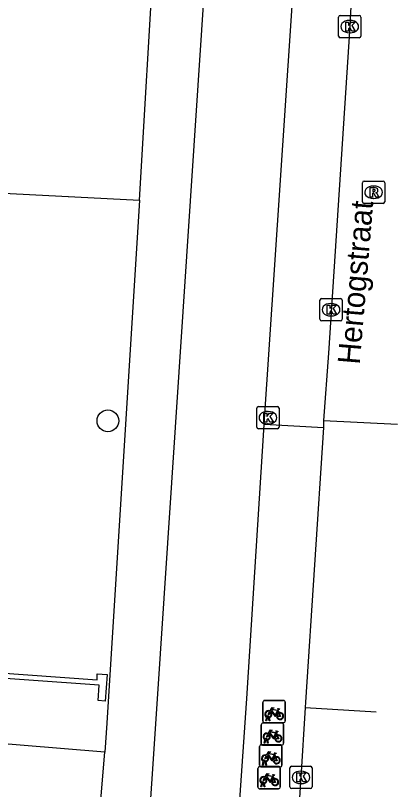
# Model space of a CAD drawing. Extents: x 161087 to 161922, y 382574 to 383873.
# Drawn here: x 161852.97 to 161870.14, y 382747.01 to 382781.78 of the extents above; entities that cross this region are included whole.
import ezdxf

# ---------------------------------------------------------------- set-up
doc = ezdxf.new("R2010")
doc.units = 0
for name, color, linetype in [('IMGEO_Berm_open', 7, 'Continuous'), ('IMGEO_Boom', 7, 'Continuous'), ('IMGEO_Fietsenrek', 7, 'Continuous'), ('IMGEO_Fietspad_gesloten', 7, 'Continuous'), ('IMGEO_Kolk', 7, 'Continuous'), ('IMGEO_Muur', 7, 'Continuous'), ('IMGEO_Openbare_ruimte_label', 7, 'Continuous'), ('IMGEO_Pand', 7, 'Continuous'), ('IMGEO_Rijbaan_lokaal_gesloten', 7, 'Continuous'), ('IMGEO_Rijbaan_lokaal_open', 7, 'Continuous'), ('IMGEO_Rioolput', 7, 'Continuous'), ('IMGEO_Voetpad_open', 7, 'Continuous')]:
    doc.layers.add(name, color=color, linetype=linetype)

msp = doc.modelspace()

# ---------------------------------------------------------------- linework, layer by layer
at = {"layer": 'IMGEO_Berm_open'}
msp.add_lwpolyline([(161864.145, 382763.415), (161866.811, 382763.275)], dxfattribs=at)
at = {"layer": 'IMGEO_Boom'}
msp.add_circle((161857.12, 382763.571), 0.489, dxfattribs=at)
at = {"layer": 'IMGEO_Fietsenrek'}
for p, q in [((161864.092, 382750.087), (161864.092, 382750.928)), ((161864.092, 382750.928), (161864.092, 382750.087)), ((161864.167, 382751.012), (161865.008, 382751.012)), ((161865.008, 382751.012), (161864.167, 382751.012)), ((161865.092, 382750.937), (161865.092, 382750.096)), ((161865.092, 382750.096), (161865.092, 382750.937)), ((161864.779, 382750.561), (161864.815, 382750.466)), ((161864.219, 382750.096), (161864.258, 382750.256)), ((161864.253, 382750.096), (161864.219, 382750.096)), ((161864.288, 382750.244), (161864.253, 382750.096)), ((161864.33, 382750.268), (161864.329, 382750.272)), ((161864.371, 382750.096), (161864.337, 382750.238)), ((161864.361, 382750.279), (161864.362, 382750.272)), ((161864.369, 382750.242), (161864.404, 382750.096)), ((161864.404, 382750.096), (161864.371, 382750.096)), ((161864.016, 382749.08), (161864.016, 382749.921)), ((161864.016, 382749.921), (161864.016, 382749.08)), ((161864.091, 382750.005), (161864.932, 382750.005)), ((161864.932, 382750.005), (161864.091, 382750.005)), ((161865.017, 382750.012), (161864.176, 382750.012)), ((161864.176, 382750.012), (161865.017, 382750.012)), ((161865.016, 382749.93), (161865.016, 382749.089)), ((161865.016, 382749.089), (161865.016, 382749.93)), ((161864.703, 382749.554), (161864.739, 382749.459)), ((161864.017, 382749.026), (161864.858, 382749.026)), ((161864.858, 382749.026), (161864.017, 382749.026)), ((161864.941, 382749.005), (161864.1, 382749.005)), ((161864.1, 382749.005), (161864.941, 382749.005)), ((161864.143, 382749.089), (161864.182, 382749.249)), ((161864.177, 382749.089), (161864.143, 382749.089)), ((161864.212, 382749.237), (161864.177, 382749.089)), ((161864.254, 382749.261), (161864.253, 382749.265)), ((161864.295, 382749.089), (161864.261, 382749.231)), ((161864.285, 382749.272), (161864.286, 382749.265)), ((161864.293, 382749.235), (161864.328, 382749.089)), ((161864.328, 382749.089), (161864.295, 382749.089)), ((161863.942, 382748.101), (161863.942, 382748.942)), ((161863.942, 382748.942), (161863.942, 382748.101)), ((161864.942, 382748.951), (161864.942, 382748.11)), ((161864.942, 382748.11), (161864.942, 382748.951)), ((161864.629, 382748.575), (161864.665, 382748.48)), ((161863.868, 382747.122), (161863.868, 382747.963)), ((161863.868, 382747.963), (161863.868, 382747.122)), ((161863.943, 382748.047), (161864.784, 382748.047)), ((161864.784, 382748.047), (161863.943, 382748.047)), ((161864.867, 382748.026), (161864.026, 382748.026)), ((161864.026, 382748.026), (161864.867, 382748.026)), ((161864.069, 382748.11), (161864.108, 382748.27)), ((161864.103, 382748.11), (161864.069, 382748.11)), ((161864.138, 382748.258), (161864.103, 382748.11)), ((161864.18, 382748.282), (161864.179, 382748.286)), ((161864.221, 382748.11), (161864.187, 382748.252)), ((161864.211, 382748.293), (161864.212, 382748.286)), ((161864.219, 382748.256), (161864.254, 382748.11)), ((161864.254, 382748.11), (161864.221, 382748.11)), ((161864.868, 382747.972), (161864.868, 382747.131)), ((161864.868, 382747.131), (161864.868, 382747.972)), ((161863.995, 382747.131), (161864.034, 382747.291)), ((161864.064, 382747.279), (161864.029, 382747.131)), ((161864.106, 382747.303), (161864.105, 382747.307)), ((161864.147, 382747.131), (161864.113, 382747.273)), ((161864.137, 382747.314), (161864.138, 382747.307)), ((161864.145, 382747.277), (161864.18, 382747.131)), ((161864.555, 382747.596), (161864.591, 382747.501)), ((161864.793, 382747.047), (161863.952, 382747.047)), ((161863.952, 382747.047), (161864.793, 382747.047)), ((161864.029, 382747.131), (161863.995, 382747.131)), ((161864.18, 382747.131), (161864.147, 382747.131))]:
    msp.add_line(p, q, dxfattribs=at)
for points in [[(161864.426, 382750.486), (161864.374, 382750.396), (161864.334, 382750.371), (161864.335, 382750.418), (161864.39, 382750.512)], [(161864.405, 382750.538), (161864.5, 382750.702), (161864.586, 382750.688), (161864.588, 382750.679), (161864.532, 382750.668), (161864.505, 382750.623), (161864.761, 382750.582)], [(161864.701, 382750.294), (161864.651, 382750.294), (161864.46, 382750.545), (161864.441, 382750.513)], [(161864.748, 382750.557), (161864.491, 382750.598), (161864.474, 382750.569), (161864.641, 382750.349), (161864.748, 382750.557)], [(161864.796, 382750.459), (161864.766, 382750.536), (161864.657, 382750.318), (161864.7, 382750.318)], [(161864.73, 382750.318), (161864.85, 382750.317), (161864.806, 382750.431)], [(161864.826, 382750.438), (161864.881, 382750.293), (161864.731, 382750.293)], [(161864.761, 382750.582), (161864.786, 382750.631), (161864.78, 382750.635), (161864.757, 382750.639), (161864.745, 382750.646), (161864.744, 382750.649), (161864.746, 382750.654), (161864.841, 382750.639), (161864.843, 382750.629), (161864.833, 382750.616), (161864.821, 382750.61), (161864.807, 382750.616), (161864.779, 382750.561)], [(161864.329, 382749.531), (161864.424, 382749.695), (161864.51, 382749.681), (161864.512, 382749.672), (161864.456, 382749.661), (161864.429, 382749.616), (161864.685, 382749.575)], [(161864.35, 382749.479), (161864.298, 382749.389), (161864.258, 382749.364), (161864.259, 382749.411), (161864.314, 382749.505)], [(161864.625, 382749.287), (161864.575, 382749.287), (161864.384, 382749.538), (161864.365, 382749.506)], [(161864.672, 382749.55), (161864.415, 382749.591), (161864.398, 382749.562), (161864.565, 382749.342), (161864.672, 382749.55)], [(161864.72, 382749.452), (161864.69, 382749.529), (161864.581, 382749.311), (161864.624, 382749.311)], [(161864.654, 382749.311), (161864.774, 382749.31), (161864.73, 382749.424)], [(161864.75, 382749.431), (161864.805, 382749.286), (161864.655, 382749.286)], [(161864.685, 382749.575), (161864.71, 382749.624), (161864.704, 382749.628), (161864.681, 382749.632), (161864.669, 382749.639), (161864.668, 382749.642), (161864.67, 382749.647), (161864.765, 382749.632), (161864.767, 382749.622), (161864.757, 382749.609), (161864.745, 382749.603), (161864.731, 382749.609), (161864.703, 382749.554)], [(161864.255, 382748.552), (161864.35, 382748.716), (161864.436, 382748.702), (161864.438, 382748.693), (161864.382, 382748.682), (161864.355, 382748.637), (161864.611, 382748.596)], [(161864.611, 382748.596), (161864.636, 382748.645), (161864.63, 382748.649), (161864.607, 382748.653), (161864.595, 382748.66), (161864.594, 382748.663), (161864.596, 382748.668), (161864.691, 382748.653), (161864.693, 382748.643), (161864.683, 382748.63), (161864.671, 382748.624), (161864.657, 382748.63), (161864.629, 382748.575)], [(161864.276, 382748.5), (161864.224, 382748.41), (161864.184, 382748.385), (161864.185, 382748.432), (161864.24, 382748.526)], [(161864.551, 382748.308), (161864.501, 382748.308), (161864.31, 382748.559), (161864.291, 382748.527)], [(161864.598, 382748.571), (161864.341, 382748.612), (161864.324, 382748.583), (161864.491, 382748.363), (161864.598, 382748.571)], [(161864.646, 382748.473), (161864.616, 382748.55), (161864.507, 382748.332), (161864.55, 382748.332)], [(161864.58, 382748.332), (161864.7, 382748.331), (161864.656, 382748.445)], [(161864.676, 382748.452), (161864.731, 382748.307), (161864.581, 382748.307)], [(161864.181, 382747.573), (161864.276, 382747.737), (161864.362, 382747.723), (161864.364, 382747.714), (161864.308, 382747.703), (161864.281, 382747.658), (161864.537, 382747.617)], [(161864.524, 382747.592), (161864.267, 382747.633), (161864.25, 382747.604), (161864.417, 382747.384), (161864.524, 382747.592)], [(161864.537, 382747.617), (161864.562, 382747.666), (161864.556, 382747.67), (161864.533, 382747.674), (161864.521, 382747.681), (161864.52, 382747.684), (161864.522, 382747.689), (161864.617, 382747.674), (161864.619, 382747.664), (161864.609, 382747.651), (161864.597, 382747.645), (161864.583, 382747.651), (161864.555, 382747.596)], [(161864.202, 382747.521), (161864.15, 382747.431), (161864.11, 382747.406), (161864.111, 382747.453), (161864.166, 382747.547)], [(161864.477, 382747.329), (161864.427, 382747.329), (161864.236, 382747.58), (161864.217, 382747.548)], [(161864.572, 382747.494), (161864.542, 382747.571), (161864.433, 382747.353), (161864.476, 382747.353)], [(161864.506, 382747.353), (161864.626, 382747.352), (161864.582, 382747.466)], [(161864.602, 382747.473), (161864.657, 382747.328), (161864.507, 382747.328)]]:
    msp.add_lwpolyline(points, dxfattribs=at)
for centre, radius, start, end in [((161864.17, 382750.934), 0.0779, 92.4484, 184.2845), ((161864.17, 382750.934), 0.0779, 92.4484, 184.2845), ((161865.014, 382750.934), 0.0779, 2.4484, 94.2845), ((161865.014, 382750.934), 0.0779, 2.4484, 94.2845), ((161864.332, 382750.397), 0.159, 62.6766, 242.1369), ((161864.332, 382750.397), 0.129, 63.3192, 238.903), ((161864.332, 382750.397), 0.129, 283.6043, 43.4302), ((161864.332, 382750.397), 0.159, 283.5766, 46.6042), ((161864.859, 382750.313), 0.159, 113.3408, 178.3217), ((161864.859, 382750.313), 0.159, 187.0065, 105.7708), ((161864.859, 382750.313), 0.129, 113.923, 177.9556), ((161864.859, 382750.313), 0.129, 188.6715, 104.5883), ((161864.17, 382750.09), 0.0779, 182.4484, 274.2845), ((161864.17, 382750.09), 0.0779, 182.4484, 274.2845), ((161864.312, 382750.268), 0.0499, 12.8025, 158.6934), ((161864.332, 382750.397), 0.159, 253.9967, 271.7867), ((161864.312, 382750.268), 0.0174, 12.8025, 163.4502), ((161864.332, 382750.397), 0.129, 253.415, 269.0204), ((161865.014, 382750.09), 0.0779, 272.4484, 4.2845), ((161865.014, 382750.09), 0.0779, 272.4484, 4.2845), ((161864.094, 382749.927), 0.0779, 92.4484, 184.2845), ((161864.094, 382749.927), 0.0779, 92.4484, 184.2845), ((161864.938, 382749.927), 0.0779, 2.4484, 94.2845), ((161864.938, 382749.927), 0.0779, 2.4484, 94.2845), ((161864.256, 382749.39), 0.159, 62.6766, 242.1369), ((161864.256, 382749.39), 0.129, 63.3192, 238.903), ((161864.256, 382749.39), 0.129, 283.6043, 43.4302), ((161864.256, 382749.39), 0.159, 283.5766, 46.6042), ((161864.783, 382749.306), 0.159, 113.3408, 178.3217), ((161864.783, 382749.306), 0.159, 187.0065, 105.7708), ((161864.783, 382749.306), 0.129, 113.923, 177.9556), ((161864.783, 382749.306), 0.129, 188.6715, 104.5883), ((161864.02, 382748.948), 0.0779, 92.4484, 184.2845), ((161864.02, 382748.948), 0.0779, 92.4484, 184.2845), ((161864.094, 382749.083), 0.0779, 182.4484, 274.2845), ((161864.094, 382749.083), 0.0779, 182.4484, 274.2845), ((161864.236, 382749.261), 0.0499, 12.8025, 158.6934), ((161864.256, 382749.39), 0.159, 253.9967, 271.7867), ((161864.236, 382749.261), 0.0174, 12.8025, 163.4502), ((161864.256, 382749.39), 0.129, 253.415, 269.0204), ((161864.864, 382748.948), 0.0779, 2.4484, 94.2845), ((161864.864, 382748.948), 0.0779, 2.4484, 94.2845), ((161864.938, 382749.083), 0.0779, 272.4484, 4.2845), ((161864.938, 382749.083), 0.0779, 272.4484, 4.2845), ((161864.182, 382748.411), 0.159, 62.6766, 242.1369), ((161864.182, 382748.411), 0.129, 63.3192, 238.903), ((161864.162, 382748.282), 0.0499, 12.8025, 158.6934), ((161864.162, 382748.282), 0.0174, 12.8025, 163.4502), ((161864.182, 382748.411), 0.129, 283.6043, 43.4302), ((161864.182, 382748.411), 0.159, 283.5766, 46.6042), ((161864.709, 382748.327), 0.159, 113.3408, 178.3217), ((161864.709, 382748.327), 0.159, 187.0065, 105.7708), ((161864.709, 382748.327), 0.129, 113.923, 177.9556), ((161864.709, 382748.327), 0.129, 188.6715, 104.5883), ((161863.946, 382747.969), 0.0779, 92.4484, 184.2845), ((161863.946, 382747.969), 0.0779, 92.4484, 184.2845), ((161864.02, 382748.104), 0.0779, 182.4484, 274.2845), ((161864.02, 382748.104), 0.0779, 182.4484, 274.2845), ((161864.182, 382748.411), 0.159, 253.9967, 271.7867), ((161864.182, 382748.411), 0.129, 253.415, 269.0204), ((161864.79, 382747.969), 0.0779, 2.4484, 94.2845), ((161864.79, 382747.969), 0.0779, 2.4484, 94.2845), ((161864.864, 382748.104), 0.0779, 272.4484, 4.2845), ((161864.864, 382748.104), 0.0779, 272.4484, 4.2845), ((161864.108, 382747.432), 0.159, 62.6766, 242.1369), ((161864.108, 382747.432), 0.129, 63.3192, 238.903), ((161864.088, 382747.303), 0.0499, 12.8025, 158.6934), ((161864.108, 382747.432), 0.159, 253.9967, 271.7867), ((161864.088, 382747.303), 0.0174, 12.8025, 163.4502), ((161864.108, 382747.432), 0.129, 253.415, 269.0204), ((161864.108, 382747.432), 0.129, 283.6043, 43.4302), ((161864.108, 382747.432), 0.159, 283.5766, 46.6042), ((161864.635, 382747.348), 0.159, 113.3408, 178.3217), ((161864.635, 382747.348), 0.159, 187.0065, 105.7708), ((161864.635, 382747.348), 0.129, 113.923, 177.9556), ((161864.635, 382747.348), 0.129, 188.6715, 104.5883), ((161863.946, 382747.125), 0.0779, 182.4484, 274.2845), ((161863.946, 382747.125), 0.0779, 182.4484, 274.2845), ((161864.79, 382747.125), 0.0779, 272.4484, 4.2845), ((161864.79, 382747.125), 0.0779, 272.4484, 4.2845)]:
    msp.add_arc(centre, radius, start, end, dxfattribs=at)
at = {"layer": 'IMGEO_Fietspad_gesloten'}
for points in [[(161864.583, 382830.709), (161862.087, 382792.658), (161859.377, 382751.761), (161858.204, 382734.049)], [(161864.145, 382763.415), (161865.585, 382784.899)], [(161862.676, 382741.127), (161863.359, 382751.101), (161864.144, 382763.393), (161864.145, 382763.415)]]:
    msp.add_lwpolyline(points, dxfattribs=at)
at = {"layer": 'IMGEO_Kolk'}
for p, q in [((161867.491, 382780.851), (161867.491, 382781.703)), ((161867.566, 382781.777), (161868.418, 382781.777)), ((161868.492, 382781.703), (161868.492, 382780.851)), ((161867.979, 382781.557), (161868.004, 382781.557)), ((161868.002, 382780.997), (161867.977, 382780.997)), ((161868.418, 382780.777), (161867.566, 382780.777)), ((161866.652, 382768.136), (161866.652, 382768.988)), ((161866.727, 382769.062), (161867.579, 382769.062)), ((161867.14, 382768.842), (161867.165, 382768.842)), ((161867.653, 382768.988), (161867.653, 382768.136)), ((161867.163, 382768.282), (161867.138, 382768.282)), ((161867.579, 382768.062), (161866.727, 382768.062)), ((161863.814, 382763.288), (161863.814, 382764.14)), ((161863.889, 382764.214), (161864.741, 382764.214)), ((161864.302, 382763.994), (161864.327, 382763.994)), ((161864.815, 382764.14), (161864.815, 382763.288)), ((161864.325, 382763.434), (161864.3, 382763.434)), ((161864.741, 382763.214), (161863.889, 382763.214)), ((161865.3, 382747.131), (161865.3, 382747.983)), ((161865.375, 382748.057), (161866.227, 382748.057)), ((161866.301, 382747.983), (161866.301, 382747.131)), ((161865.788, 382747.837), (161865.813, 382747.837)), ((161865.811, 382747.277), (161865.786, 382747.277)), ((161866.227, 382747.057), (161865.375, 382747.057))]:
    msp.add_line(p, q, dxfattribs=at)
for points in [[(161867.491, 382780.851), (161867.491, 382781.703)], [(161867.566, 382781.777), (161868.418, 382781.777)], [(161868.492, 382781.703), (161868.492, 382780.851)], [(161867.812, 382781.477), (161867.935, 382781.477), (161867.935, 382781.326), (161868.065, 382781.477), (161868.229, 382781.477), (161868.083, 382781.326), (161868.236, 382781.077), (161868.084, 382781.077), (161867.999, 382781.241), (161867.935, 382781.174), (161867.935, 382781.077), (161867.812, 382781.077), (161867.812, 382781.477)], [(161868.418, 382780.777), (161867.566, 382780.777)], [(161866.652, 382768.136), (161866.652, 382768.988)], [(161866.727, 382769.062), (161867.579, 382769.062)], [(161867.653, 382768.988), (161867.653, 382768.136)], [(161866.973, 382768.762), (161867.096, 382768.762), (161867.096, 382768.611), (161867.226, 382768.762), (161867.39, 382768.762), (161867.244, 382768.611), (161867.397, 382768.362), (161867.245, 382768.362), (161867.16, 382768.526), (161867.096, 382768.459), (161867.096, 382768.362), (161866.973, 382768.362), (161866.973, 382768.762)], [(161867.579, 382768.062), (161866.727, 382768.062)], [(161863.814, 382763.288), (161863.814, 382764.14)], [(161863.889, 382764.214), (161864.741, 382764.214)], [(161864.815, 382764.14), (161864.815, 382763.288)], [(161864.135, 382763.914), (161864.258, 382763.914), (161864.258, 382763.763), (161864.388, 382763.914), (161864.552, 382763.914), (161864.406, 382763.763), (161864.559, 382763.514), (161864.407, 382763.514), (161864.322, 382763.678), (161864.258, 382763.611), (161864.258, 382763.514), (161864.135, 382763.514), (161864.135, 382763.914)], [(161864.741, 382763.214), (161863.889, 382763.214)], [(161865.3, 382747.131), (161865.3, 382747.983)], [(161865.375, 382748.057), (161866.227, 382748.057)], [(161866.301, 382747.983), (161866.301, 382747.131)], [(161865.621, 382747.757), (161865.744, 382747.757), (161865.744, 382747.606), (161865.874, 382747.757), (161866.038, 382747.757), (161865.892, 382747.606), (161866.045, 382747.357), (161865.893, 382747.357), (161865.808, 382747.521), (161865.744, 382747.454), (161865.744, 382747.357), (161865.621, 382747.357), (161865.621, 382747.757)], [(161866.227, 382747.057), (161865.375, 382747.057)]]:
    msp.add_lwpolyline(points, dxfattribs=at)
for centre, start, end in [((161867.568, 382781.701), 91.552, 178.448), ((161867.568, 382781.701), 91.552, 178.448), ((161868.416, 382781.701), 1.552, 88.448), ((161868.416, 382781.701), 1.552, 88.448), ((161867.568, 382780.853), 181.552, 268.448), ((161867.568, 382780.853), 181.552, 268.448), ((161868.416, 382780.853), 271.552, 358.448), ((161868.416, 382780.853), 271.552, 358.448), ((161866.729, 382768.986), 91.552, 178.448), ((161866.729, 382768.986), 91.552, 178.448), ((161867.577, 382768.986), 1.552, 88.448), ((161867.577, 382768.986), 1.552, 88.448), ((161866.729, 382768.138), 181.552, 268.448), ((161866.729, 382768.138), 181.552, 268.448), ((161867.577, 382768.138), 271.552, 358.448), ((161867.577, 382768.138), 271.552, 358.448), ((161863.891, 382764.138), 91.552, 178.448), ((161863.891, 382764.138), 91.552, 178.448), ((161864.739, 382764.138), 1.552, 88.448), ((161864.739, 382764.138), 1.552, 88.448), ((161863.891, 382763.29), 181.552, 268.448), ((161863.891, 382763.29), 181.552, 268.448), ((161864.739, 382763.29), 271.552, 358.448), ((161864.739, 382763.29), 271.552, 358.448), ((161865.377, 382747.981), 91.552, 178.448), ((161865.377, 382747.981), 91.552, 178.448), ((161866.225, 382747.981), 1.552, 88.448), ((161866.225, 382747.981), 1.552, 88.448), ((161865.377, 382747.133), 181.552, 268.448), ((161865.377, 382747.133), 181.552, 268.448), ((161866.225, 382747.133), 271.552, 358.448), ((161866.225, 382747.133), 271.552, 358.448)]:
    msp.add_arc(centre, 0.0765, start, end, dxfattribs=at)
for centre, major_axis, ratio, start_param, end_param in [((161867.978, 382781.277), (-0.387, 0.002), 0.722429, 4.712389, 7.853982), ((161868.003, 382781.277), (-0.39, 0.002), 0.717154, 1.570796, 4.712389), ((161867.139, 382768.562), (-0.387, 0.002), 0.722429, 4.712389, 7.853982), ((161867.164, 382768.562), (-0.39, 0.002), 0.717154, 1.570796, 4.712389), ((161864.301, 382763.714), (-0.387, 0.002), 0.722429, 4.712389, 7.853982), ((161864.326, 382763.714), (-0.39, 0.002), 0.717154, 1.570796, 4.712389), ((161865.787, 382747.557), (-0.387, 0.002), 0.722429, 4.712389, 7.853982), ((161865.812, 382747.557), (-0.39, 0.002), 0.717154, 1.570796, 4.712389)]:
    msp.add_ellipse(centre, major_axis=major_axis, ratio=ratio, start_param=start_param, end_param=end_param, dxfattribs=at)
at = {"layer": 'IMGEO_Muur'}
msp.add_lwpolyline([(161844.36, 382752.828), (161856.644, 382751.943), (161856.643, 382752.212), (161857.081, 382752.181), (161856.997, 382750.984), (161856.678, 382751.007), (161856.728, 382751.706), (161844.482, 382752.573)], dxfattribs=at)
at = {"layer": 'IMGEO_Pand'}
for points in [[(161858.54, 382773.49), (161859.223, 382784.937), (161859.25, 382785.386)], [(161849.885, 382776.163), (161850.038, 382778.234), (161852.437, 382778.057), (161852.125, 382773.811), (161858.54, 382773.49)], [(161856.985, 382748.691), (161845.906, 382749.6)], [(161856.266, 382740.106), (161856.985, 382748.691)]]:
    msp.add_lwpolyline(points, dxfattribs=at)
at = {"layer": 'IMGEO_Rijbaan_lokaal_gesloten'}
for points in [[(161868.195, 382784.741), (161868.059, 382782.507), (161867.992, 382781.277), (161867.032, 382766.607), (161866.818, 382763.59)], [(161866.818, 382763.59), (161870.141, 382763.42)], [(161865.994, 382750.69), (161865.801, 382747.557), (161865.365, 382740.966)], [(161865.994, 382750.69), (161869.18, 382750.506)]]:
    msp.add_lwpolyline(points, dxfattribs=at)
at = {"layer": 'IMGEO_Rijbaan_lokaal_open'}
for points in [[(161866.811, 382763.275), (161866.01, 382750.942), (161865.994, 382750.69)], [(161866.818, 382763.59), (161866.811, 382763.275)]]:
    msp.add_lwpolyline(points, dxfattribs=at)
at = {"layer": 'IMGEO_Rioolput'}
for p, q in [((161868.565, 382773.411), (161868.565, 382774.263)), ((161868.64, 382774.337), (161869.492, 382774.337)), ((161869.053, 382774.117), (161869.078, 382774.117)), ((161869.566, 382774.263), (161869.566, 382773.411)), ((161869.492, 382773.337), (161868.64, 382773.337)), ((161869.076, 382773.557), (161869.051, 382773.557))]:
    msp.add_line(p, q, dxfattribs=at)
for points in [[(161868.565, 382773.411), (161868.565, 382774.263)], [(161868.64, 382774.337), (161869.492, 382774.337)], [(161869.154, 382774.035), (161868.902, 382774.037), (161868.902, 382773.637)], [(161869.566, 382774.263), (161869.566, 382773.411)], [(161868.902, 382773.637), (161869.026, 382773.637), (161869.026, 382773.799), (161869.037, 382773.799)], [(161869.08, 382773.956), (161869.026, 382773.956), (161869.026, 382773.875)], [(161869.026, 382773.875), (161869.078, 382773.875)], [(161869.084, 382773.77), (161869.155, 382773.637), (161869.295, 382773.637), (161869.23, 382773.763)], [(161869.492, 382773.337), (161868.64, 382773.337)]]:
    msp.add_lwpolyline(points, dxfattribs=at)
for centre, radius, start, end in [((161868.642, 382774.261), 0.0765, 91.552, 178.448), ((161868.642, 382774.261), 0.0765, 91.552, 178.448), ((161869.153, 382773.925), 0.109, 350.3612, 89.416), ((161869.49, 382774.261), 0.0765, 1.552, 88.448), ((161869.49, 382774.261), 0.0765, 1.552, 88.448), ((161869.036, 382773.746), 0.0533, 26.0293, 88.6989), ((161869.062, 382774.064), 0.19, 274.7715, 282.9687), ((161869.086, 382773.86), 0.0964, 77.0061, 93.1865), ((161869.1, 382773.917), 0.0378, 276.6634, 79.6772), ((161869.151, 382773.925), 0.112, 277.5842, 350.9817), ((161869.135, 382773.71), 0.108, 29.5134, 73.7905), ((161868.642, 382773.413), 0.0765, 181.552, 268.448), ((161868.642, 382773.413), 0.0765, 181.552, 268.448), ((161869.49, 382773.413), 0.0765, 271.552, 358.448), ((161869.49, 382773.413), 0.0765, 271.552, 358.448)]:
    msp.add_arc(centre, radius, start, end, dxfattribs=at)
for centre, major_axis, ratio, start_param, end_param in [((161869.052, 382773.837), (-0.387, 0.002), 0.722429, 4.712389, 7.853982), ((161869.077, 382773.837), (-0.39, 0.002), 0.717154, 1.570796, 4.712389)]:
    msp.add_ellipse(centre, major_axis=major_axis, ratio=ratio, start_param=start_param, end_param=end_param, dxfattribs=at)
at = {"layer": 'IMGEO_Voetpad_open'}
msp.add_lwpolyline([(161858.54, 382773.49), (161857.067, 382750), (161856.985, 382748.691)], dxfattribs=at)

# ---------------------------------------------------------------- texts
at = {"layer": 'IMGEO_Openbare_ruimte_label'}
msp.add_text('Hertogstraat', height=1, rotation=85.2411, dxfattribs=at).set_placement((161868.44, 382766.079))

doc.saveas('drawing.dxf')
